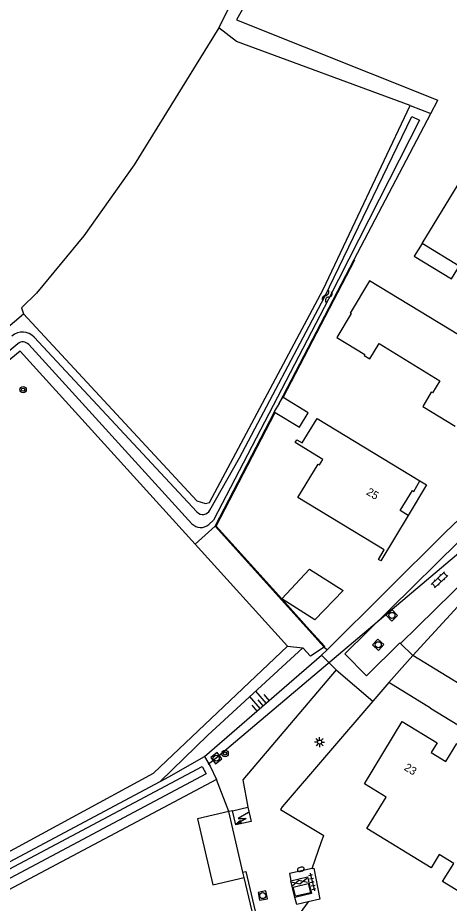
# Model space of a CAD drawing. Extents: x 136000 to 141014, y 402000 to 403500.
# Drawn here: x 137695.8 to 137749.6, y 402514.4 to 402625 of the extents above; entities that cross this region are included whole.
import ezdxf

# ---------------------------------------------------------------- set-up
doc = ezdxf.new("R2010")
doc.units = 0
for name, color, linetype in [('gg-afsc-draadraster', 7, 'Continuous'), ('gg-afsc-erfafscheiding', 7, 'Continuous'), ('gg-afsc-hekwerk', 7, 'Continuous'), ('gg-afsc-lijn draadraster', 7, 'Continuous'), ('gg-anno-huisnummerreeks BGT', 7, 'Continuous'), ('gg-bbg-bijgebouw', 7, 'Continuous'), ('gg-bbg-hoofdgebouw', 7, 'Continuous'), ('gg-bbg-luifel en loopbrug', 7, 'Continuous'), ('gg-bbg-onder overbouw', 7, 'Continuous'), ('gg-bbg-overig bouwwerk', 7, 'Continuous'), ('gg-bbg-pand overbouw', 7, 'Continuous'), ('gg-knt-bovenkant onderkant talud', 7, 'Continuous'), ('gg-knt-bronhoudergrens', 7, 'Continuous'), ('gg-knt-verharding', 7, 'Continuous'), ('gg-knt-verharding nz', 7, 'Continuous'), ('gg-kntw-bovenkant insteek waterloop', 7, 'Continuous'), ('gg-kntw-greppel-droge sloot', 7, 'Continuous'), ('gg-kntw-waterlijn', 7, 'Continuous'), ('gg-kwrk-duiker nz buis', 7, 'Continuous'), ('gg-kwrk-gemaal', 7, 'Continuous'), ('gg-kwrk-keermuur', 7, 'Continuous'), ('gt-grn-groengrens', 7, 'Continuous'), ('gt-grn-weggrens', 7, 'Continuous'), ('gt-symb-boom', 7, 'Continuous'), ('gt-symb-brandkraan', 7, 'Continuous'), ('gt-symb-gesloten verharding', 7, 'Continuous'), ('gt-symb-klinker verharding', 7, 'Continuous'), ('gt-symb-lichtmast', 7, 'Continuous'), ('gt-symb-rioolschacht', 7, 'Continuous'), ('gt-symb-talud symbool', 7, 'Continuous'), ('gt-symb-tegel verharding', 7, 'Continuous'), ('gt-symb-trafo symbool', 7, 'Continuous'), ('gt-symb-watersymbool', 7, 'Continuous')]:
    doc.layers.add(name, color=color, linetype=linetype)

# ---------------------------------------------------------------- blocks, each defined once
blk = doc.blocks.new('gt0-WA')
at = {"layer": 'gt-symb-watersymbool'}
for centre, start, end in [((-0.32, 0.02), 28.0725, 151.9275), ((0.43, 0.42), 208.0725, 331.9275), ((-0.32, -0.43), 28.0725, 151.9275), ((0.43, -0.03), 208.0725, 331.9275)]:
    blk.add_arc(centre, 0.425, start, end, dxfattribs=at)
blk = doc.blocks.new('gt0-RS')
at = {"layer": 'gt-symb-rioolschacht'}
blk.add_lwpolyline([(-0.5, -0.5), (0.5, -0.5), (0.5, 0.5), (-0.5, 0.5)], close=True, dxfattribs=at)
blk.add_circle((0, 0), 0.375, dxfattribs=at)
blk = doc.blocks.new('gt0-KL1')
at = {"layer": 'gt-symb-klinker verharding'}
for p, q in [((-1.15, 0.3), (1.15, 0.3)), ((-1, -0.3), (-1, 0.3)), ((-0.5, 0.3), (-0.5, 0.45)), ((0, -0.3), (0, 0.3)), ((0.5, 0.3), (0.5, 0.45)), ((1, -0.3), (1, 0.3)), ((-1.15, -0.3), (1.15, -0.3)), ((-0.5, -0.45), (-0.5, -0.3)), ((0.5, -0.45), (0.5, -0.3))]:
    blk.add_line(p, q, dxfattribs=at)
blk = doc.blocks.new('gt0-BOOM')
at = {"layer": 'gt-symb-boom'}
for radius in [0.4, 0.2]:
    blk.add_circle((0, 0), radius, dxfattribs=at)
blk = doc.blocks.new('gt0-HSP')
at = {"layer": 'gt-symb-trafo symbool'}
for points in [[(0.77, 0.75), (-0.53, 0), (0.47, 0), (-0.83, -0.75)], [(-0.22, -0.24), (-0.83, -0.75), (-0.08, -0.48)]]:
    blk.add_lwpolyline(points, dxfattribs=at)
blk = doc.blocks.new('gt0-TALUD_1')
at = {"layer": 'gt-symb-talud symbool'}
for p, q in [((-0.5, -2), (-0.5, 0)), ((0, -1), (0, 0)), ((-1, -1), (-1, 0)), ((0.5, -2), (0.5, 0)), ((1, -1), (1, 0))]:
    blk.add_line(p, q, dxfattribs=at)
blk = doc.blocks.new('gt0-GESVH1')
at = {"layer": 'gt-symb-gesloten verharding'}
for p, q in [((-0.99, -0.26), (0.01, 0.24)), ((0.01, -0.26), (-0.99, 0.24)), ((0.01, 0.24), (1.01, -0.26)), ((1.01, 0.24), (0.01, -0.26))]:
    blk.add_line(p, q, dxfattribs=at)
blk = doc.blocks.new('gt0-TEG1')
at = {"layer": 'gt-symb-tegel verharding'}
for p, q in [((-1.12, 0), (1.12, 0)), ((-0.9, -0.25), (-0.9, 0.25)), ((-0.45, -0.25), (-0.45, 0.25)), ((0, -0.25), (0, 0.25)), ((0.45, -0.25), (0.45, 0.25)), ((0.9, -0.25), (0.9, 0.25))]:
    blk.add_line(p, q, dxfattribs=at)
blk = doc.blocks.new('gt0-BR')
at = {"layer": 'gt-symb-brandkraan'}
for centre, radius, start, end in [((-0.24, 0), 0.206, 107.5669, 252.4331), ((0.6, -2.66), 3, 106.892, 107.5669), ((0, -0.69), 0.938, 73.108, 106.892), ((-0.6, -2.66), 3, 72.4331, 73.108), ((0.24, 0), 0.206, 287.567, 72.4331), ((0.6, 2.66), 3, 252.4331, 253.108), ((0, 0.69), 0.938, 253.108, 286.8921), ((-0.6, 2.66), 3, 286.8921, 287.567)]:
    blk.add_arc(centre, radius, start, end, dxfattribs=at)
blk = doc.blocks.new('gt0-LMAST')
at = {"layer": 'gt-symb-lichtmast'}
for p, q in [((-0.18, 0.17), (-0.45, 0.44)), ((0, 0.25), (0, 0.62)), ((0.17, 0.17), (0.44, 0.44)), ((-0.25, 0), (-0.63, 0)), ((-0.18, -0.18), (-0.45, -0.45)), ((0, -0.25), (0, -0.63)), ((0.44, -0.45), (0.17, -0.18)), ((0.25, 0), (0.62, 0))]:
    blk.add_line(p, q, dxfattribs=at)
blk.add_circle((0, 0), 0.25, dxfattribs=at)

msp = doc.modelspace()

# ---------------------------------------------------------------- linework, layer by layer
at = {"layer": 'gg-afsc-draadraster'}
msp.add_lwpolyline([(137713.53, 402529.61), (137719.51, 402535.41), (137731.35, 402546.3)], dxfattribs=at)
at = {"layer": 'gg-afsc-erfafscheiding'}
for p, q in [((137720.57, 402529.87), (137606.85, 402469.55)), ((137722.1, 402525.88), (137720.57, 402529.87)), ((137728.21, 402500), (137724.02, 402517.64))]:
    msp.add_line(p, q, dxfattribs=at)
at = {"layer": 'gg-afsc-hekwerk'}
msp.add_lwpolyline([(137747.28, 402538.79), (137781.95, 402517.64), (137784.27, 402521.45)], dxfattribs=at)
at = {"layer": 'gg-afsc-lijn draadraster'}
msp.add_lwpolyline([(137713.53, 402529.61), (137719.51, 402535.41), (137731.35, 402546.3)], dxfattribs=at)
at = {"layer": 'gg-bbg-bijgebouw'}
for p, q in [((137727.83, 402575.76), (137727.92, 402575.71)), ((137723.87, 402518.29), (137722.1, 402525.88)), ((137724.02, 402517.64), (137723.87, 402518.29))]:
    msp.add_line(p, q, dxfattribs=at)
for points in [[(137728.39, 402576.83), (137727.76, 402575.81), (137727.83, 402575.76)], [(137727.92, 402575.71), (137730.93, 402573.85), (137732.03, 402575.64), (137728.89, 402577.58)], [(137728.39, 402576.83), (137728.86, 402577.59), (137728.89, 402577.58)], [(137722.1, 402525.88), (137718.21, 402524.97), (137720.13, 402516.73), (137724.02, 402517.64)]]:
    msp.add_lwpolyline(points, dxfattribs=at)
at = {"layer": 'gg-bbg-hoofdgebouw'}
for p, q in [((137744.5, 402562.85), (137741.08, 402557.18)), ((137752.18, 402541.01), (137745.07, 402545.36))]:
    msp.add_line(p, q, dxfattribs=at)
for points in [[(137746.24, 402596.8), (137751.65, 402605.67), (137756.27, 402602.84), (137754.65, 402600.18)], [(137752.04, 402593.3), (137753.36, 402595.48), (137752.21, 402596.15), (137750.86, 402593.97), (137746.24, 402596.8)], [(137759.59, 402580.07), (137739.69, 402592.12), (137737.27, 402588.11), (137737.39, 402588.04), (137735.59, 402585.06), (137739.09, 402582.94), (137739.02, 402582.83), (137739.72, 402582.39), (137740.87, 402584.29), (137748.48, 402579.66), (137747.54, 402578.13), (137747.38, 402578.23), (137746.32, 402576.46), (137750.39, 402573.99)], [(137741.08, 402557.18), (137740.79, 402557.35), (137741.51, 402558.53), (137730.75, 402565.09), (137733.28, 402569.23), (137733.42, 402569.14), (137733.84, 402569.82), (137730.4, 402571.96), (137730.62, 402572.3), (137731.28, 402571.89), (137733.16, 402574.96), (137745.97, 402567.15)], [(137745.07, 402545.36), (137751.64, 402552.45), (137752.07, 402552.2), (137751.96, 402552.02), (137752.56, 402551.68), (137755.72, 402556.92), (137761.3, 402553.52), (137761.08, 402553.15), (137759.86, 402553.89), (137759.27, 402552.93), (137767.82, 402547.82)], [(137756.79, 402512.26), (137748.81, 402517.14), (137750.19, 402519.39), (137748.39, 402520.49), (137747.38, 402518.82), (137739.34, 402523.73), (137741.74, 402527.67), (137739.06, 402529.32), (137743.77, 402537.1), (137748.13, 402534.45), (137747.39, 402533.23), (137749.19, 402532.13), (137750.57, 402534.38), (137758.61, 402529.48)]]:
    msp.add_lwpolyline(points, dxfattribs=at)
at = {"layer": 'gg-bbg-luifel en loopbrug'}
for points in [[(137746.24, 402596.8), (137745.26, 402595.21), (137749.9, 402592.38), (137750.9, 402593.99), (137752.04, 402593.3)], [(137728.74, 402552.41), (137732.18, 402556.12), (137736.39, 402553.47), (137732.86, 402549.8), (137728.74, 402552.41)]]:
    msp.add_lwpolyline(points, dxfattribs=at)
at = {"layer": 'gg-bbg-onder overbouw'}
msp.add_lwpolyline([(137744.5, 402562.85), (137743.52, 402563.46), (137745.03, 402565.94), (137745.2, 402565.83), (137745.97, 402567.15)], dxfattribs=at)
at = {"layer": 'gg-bbg-overig bouwwerk'}
msp.add_line((137722.57, 402525.94), (137724.48, 402526.4), dxfattribs=at)
msp.add_lwpolyline([(137724.48, 402526.4), (137724.89, 402524.64), (137722.97, 402524.19), (137722.57, 402525.94)], dxfattribs=at)
at = {"layer": 'gg-bbg-pand overbouw'}
msp.add_lwpolyline([(137745.97, 402567.15), (137746.8, 402566.66), (137744.5, 402562.85)], dxfattribs=at)
at = {"layer": 'gg-knt-bovenkant onderkant talud'}
msp.add_line((137719.06, 402532.73), (137733.7, 402545.38), dxfattribs=at)
at = {"layer": 'gg-knt-bronhoudergrens'}
for points in [[(137720.86, 402623.72), (137710.29, 402606.64), (137704.01, 402597.77), (137698.11, 402590.61), (137696.22, 402588.78), (137696.49, 402588.03)], [(137655.46, 402500.47), (137665.54, 402505.24), (137663.16, 402509.95), (137665.12, 402511.33), (137667.92, 402506.35), (137712.69, 402530.64), (137729.46, 402546.52)]]:
    msp.add_lwpolyline(points, dxfattribs=at)
at = {"layer": 'gg-knt-verharding'}
for p, q in [((137750.9, 402562.41), (137749.13, 402560.69)), ((137734.38, 402546.05), (137749.13, 402560.69)), ((137757.78, 402560.86), (137743.55, 402546.84)), ((137733.7, 402545.38), (137734.38, 402546.05)), ((137745.07, 402545.36), (137743.55, 402546.84)), ((137735.53, 402543.55), (137733.7, 402545.38)), ((137745.07, 402545.36), (137742.1, 402541.96)), ((137742.1, 402541.96), (137740.1, 402539.63)), ((137722.57, 402525.94), (137722.1, 402525.88)), ((137728.56, 402526.1), (137733.96, 402522.86)), ((137733.7, 402522.14), (137733.96, 402522.86)), ((137732.5, 402518.76), (137733.7, 402522.14)), ((137730.34, 402515.14), (137729.84, 402517.23)), ((137732.01, 402514.59), (137729.31, 402510.86))]:
    msp.add_line(p, q, dxfattribs=at)
for points in [[(137735.53, 402543.55), (137723.87, 402529.83), (137724.48, 402526.4)], [(137740.1, 402539.63), (137728.77, 402526.44), (137728.56, 402526.1)], [(137723.87, 402518.29), (137724.25, 402518.39), (137728.57, 402500)], [(137732.5, 402518.76), (137729.67, 402518.12), (137729.84, 402517.23)], [(137732.5, 402518.76), (137732.71, 402518.8), (137733.48, 402514.94), (137732.01, 402514.59)], [(137729.84, 402517.23), (137731.93, 402517.72), (137732.43, 402515.62), (137730.34, 402515.14)], [(137732.01, 402514.59), (137730.59, 402514.26), (137730.34, 402515.14)]]:
    msp.add_lwpolyline(points, dxfattribs=at)
at = {"layer": 'gg-knt-verharding nz'}
msp.add_lwpolyline([(137759.73, 402568.25), (137756.52, 402565.22), (137736.59, 402545.55), (137739.3, 402542.8), (137743.47, 402546.93), (137743.55, 402546.84)], dxfattribs=at)
at = {"layer": 'gg-kntw-bovenkant insteek waterloop'}
for p, q in [((137747.35, 402613.02), (137748.22, 402614.68)), ((137744.75, 402614.05), (137747.35, 402613.02)), ((137737.76, 402594.8), (137747.35, 402613.02)), ((137720.4, 402561.48), (137717.93, 402559.24))]:
    msp.add_line(p, q, dxfattribs=at)
for points in [[(137696.49, 402588.03), (137718.11, 402564.66), (137719.19, 402564.35), (137719.7, 402564.46), (137733.91, 402591.05), (137744.75, 402614.05)], [(137589.07, 402494.03), (137589.63, 402494.91), (137601.74, 402505.34), (137619.43, 402521.24), (137638.4, 402537.59), (137657.37, 402553.87), (137676.85, 402571.33), (137696.49, 402588.03)], [(137717.93, 402559.24), (137696.07, 402583.35), (137681.21, 402571.15), (137665.86, 402557.34), (137647.15, 402541.16), (137626.63, 402523.23), (137621.07, 402518.27)], [(137713.53, 402529.61), (137714.64, 402530.2), (137719.06, 402532.73)], [(137719.06, 402532.73), (137719.8, 402531.52), (137720.57, 402529.87)], [(137638.79, 402489.81), (137640.38, 402490.63), (137713.53, 402529.61)]]:
    msp.add_lwpolyline(points, dxfattribs=at)
at = {"layer": 'gg-kntw-greppel-droge sloot'}
for q in [(137717.93, 402559.24), (137731.35, 402546.3)]:
    msp.add_line((137729.46, 402546.52), q, dxfattribs=at)
for points in [[(137720.86, 402623.72), (137734.02, 402649.73), (137741.13, 402662.51), (137741.19, 402663.73), (137740.79, 402664.47), (137738.13, 402666.01), (137735.41, 402667.44)], [(137743.67, 402665.72), (137744.49, 402665.01), (137745.07, 402663.89), (137723.09, 402624.74), (137748.22, 402614.68)], [(137744.75, 402614.05), (137723.08, 402622.02), (137720.86, 402623.72)], [(137734.03, 402546.41), (137732.31, 402545.25), (137731.35, 402546.3)]]:
    msp.add_lwpolyline(points, dxfattribs=at)
at = {"layer": 'gg-kntw-waterlijn'}
for p, q in [((137697.82, 402585.09), (137718.14, 402563.28)), ((137717.5, 402561.81), (137697.14, 402584.19)), ((137720.22, 402562.25), (137719.61, 402561.7))]:
    msp.add_line(p, q, dxfattribs=at)
for points in [[(137719.76, 402563.51), (137723.45, 402570.02), (137734.07, 402590.09), (137744.96, 402612.64), (137745.91, 402612.2), (137734.56, 402589.83), (137720.22, 402562.25)], [(137695.76, 402584.28), (137681.35, 402572.26), (137640.38, 402536.38), (137591.81, 402493.47), (137590.95, 402494.48)], [(137605.55, 402471.28), (137718.78, 402531.5), (137719.28, 402530.57), (137605.94, 402470.28), (137605.55, 402471.28)]]:
    msp.add_lwpolyline(points, dxfattribs=at)
for centre, radius, start, end in [((137696.35, 402583.73), 2, 42.9673, 130.8357), ((137696.4, 402583.51), 0.999, 42.2742, 129.8496), ((137718.87, 402563.96), 0.999, 222.9491, 332.8556), ((137718.61, 402562.82), 1.5, 222.3301, 311.5786)]:
    msp.add_arc(centre, radius, start, end, dxfattribs=at)
at = {"layer": 'gg-kwrk-duiker nz buis'}
msp.add_lwpolyline([(137586.1, 402722.93), (137594.72, 402726.78), (137816.25, 402641.33), (137813.99, 402635.86), (137813.3, 402634.71), (137788.19, 402598.22), (137773.49, 402580.71), (137757.79, 402563.99), (137720.54, 402532.55), (137719.54, 402531.76)], dxfattribs=at)
at = {"layer": 'gg-kwrk-gemaal'}
msp.add_lwpolyline([(137732.03, 402516.86), (137732.3, 402515.71), (137730.42, 402515.28), (137730.14, 402516.42), (137732.03, 402516.86)], dxfattribs=at)
at = {"layer": 'gg-kwrk-keermuur'}
for p, q in [((137728.39, 402576.83), (137737.76, 402594.8)), ((137720.4, 402561.48), (137727.83, 402575.76)), ((137734.03, 402546.41), (137720.4, 402561.48)), ((137732.24, 402548.53), (137728.74, 402552.41))]:
    msp.add_line(p, q, dxfattribs=at)
for points in [[(137728.89, 402577.58), (137737.85, 402594.75), (137737.76, 402594.8)], [(137728.74, 402552.41), (137720.52, 402561.5), (137727.92, 402575.71)], [(137734.03, 402546.41), (137734.1, 402546.48), (137732.24, 402548.53)]]:
    msp.add_lwpolyline(points, dxfattribs=at)
at = {"layer": 'gt-grn-groengrens'}
for p, q in [((137734.03, 402546.41), (137734.26, 402546.18)), ((137734.26, 402546.18), (137734.38, 402546.05)), ((137747.28, 402538.79), (137742.1, 402541.96))]:
    msp.add_line(p, q, dxfattribs=at)
at = {"layer": 'gt-grn-weggrens'}
msp.add_line((137735.53, 402543.55), (137740.1, 402539.63), dxfattribs=at)

# ---------------------------------------------------------------- block references
at = {"layer": 'gt-symb-boom'}
for p in [(137696.43, 402578.54), (137721.65, 402533.11)]:
    msp.add_blockref('gt0-BOOM', p, dxfattribs=at)
at = {"layer": 'gt-symb-brandkraan', "rotation": -163.79481462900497}
msp.add_blockref('gt0-BR', (137731.1, 402518.66), dxfattribs=at)
at = {"layer": 'gt-symb-gesloten verharding', "rotation": 13.299584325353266}
msp.add_blockref('gt0-GESVH1', (137730.91, 402517.05), dxfattribs=at)
at = {"layer": 'gt-symb-klinker verharding', "rotation": 43.21767957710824}
msp.add_blockref('gt0-KL1', (137748.43, 402554.79), dxfattribs=at)
at = {"layer": 'gt-symb-lichtmast'}
msp.add_blockref('gt0-LMAST', (137733.45, 402534.54), dxfattribs=at)
at = {"layer": 'gt-symb-rioolschacht'}
for p, rotation in [((137742.48, 402550.36), -47.30018868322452), ((137740.77, 402546.7), -131.9284266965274), ((137720.55, 402532.53), -53.21030035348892), ((137726.35, 402515.37), 11.5907368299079)]:
    msp.add_blockref('gt0-RS', p, dxfattribs=dict(at, rotation=rotation))
at = {"layer": 'gt-symb-talud symbool', "xscale": 1.0000499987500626, "yscale": 1.0000499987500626, "rotation": -139.46084825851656}
msp.add_blockref('gt0-TALUD_1', (137726.38, 402539.05), dxfattribs=at)
at = {"layer": 'gt-symb-tegel verharding', "rotation": -76.35276166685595}
msp.add_blockref('gt0-TEG1', (137732.54, 402517.07), dxfattribs=at)
at = {"layer": 'gt-symb-trafo symbool'}
msp.add_blockref('gt0-HSP', (137723.8, 402524.99), dxfattribs=at)
at = {"layer": 'gt-symb-watersymbool', "rotation": -116.7444202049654}
msp.add_blockref('gt0-WA', (137734.42, 402590.25), dxfattribs=at)

# ---------------------------------------------------------------- texts
at = {"layer": 'gg-anno-huisnummerreeks BGT'}
for s, rotation, p in [('25', 328.7, (137739.19, 402565.52)), ('23', 328.8, (137743.91, 402531.11))]:
    msp.add_text(s, height=1, rotation=rotation, dxfattribs=at).set_placement(p)

doc.saveas('drawing.dxf')
